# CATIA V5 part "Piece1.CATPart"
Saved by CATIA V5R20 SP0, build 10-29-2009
Part number: Piece1
Bounding box of the stored display mesh (mm): x 0 to 20, y 0 to 7.024, z -18.726 to 0
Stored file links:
  C:\Users\ASUS\Desktop\Think Motion IAO\Piece1.CATPart
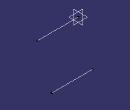
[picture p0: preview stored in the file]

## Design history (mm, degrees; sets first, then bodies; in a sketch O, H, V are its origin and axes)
Body1 (main body)
  Point1 "Point.A": stored without definition
  Line1: type PtDir, RefPoint Point1, Direction yz-plane, Start 0, End 20
  Point2 "Point.O": stored without definition
  Line2: type PtDir, RefPoint Point2, Direction yz-plane, Start 0, End 20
